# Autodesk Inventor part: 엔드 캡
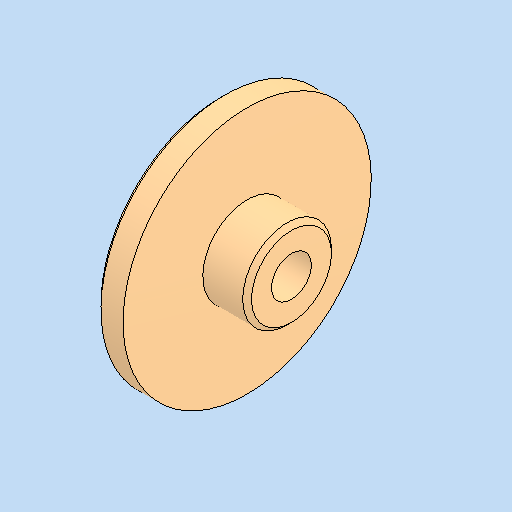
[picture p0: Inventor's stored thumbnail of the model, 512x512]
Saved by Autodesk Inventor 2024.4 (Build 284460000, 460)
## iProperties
Created: 2025-11
Part Number: 엔드 캡
Material: 강철, 연강
Document SubType Name: Modeling
Designer: home
Density: 7.85 g/cm^3
Appearance: 기본값
Author: jhkim
Sending System: Autodesk Inventor 2026
Preprocessor: ST-DEVELOPER v20.1
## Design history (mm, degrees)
feature "솔리드1"
node "솔리드2"
